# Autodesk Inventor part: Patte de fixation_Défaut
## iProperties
Shininess: 64.0
Length Units: 11269
Angle Units: 11279
Time Units: 11290
Mass Units: 11283
Length Display Precision: 3
Angle Display Precision: 2
Compacted: True
Part Number: Patte de fixation_Défaut
Document SubType Name: Modeling
Created: 2006-01
Material: Par défaut
Designer: Fricot
Density: 0.0
Volumn: 0.0
Area: 0.0
PropertySet Name: Model Information
Control State: 0
Master: False
Checked Out: False
Author: Fricot
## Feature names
1. Base1
